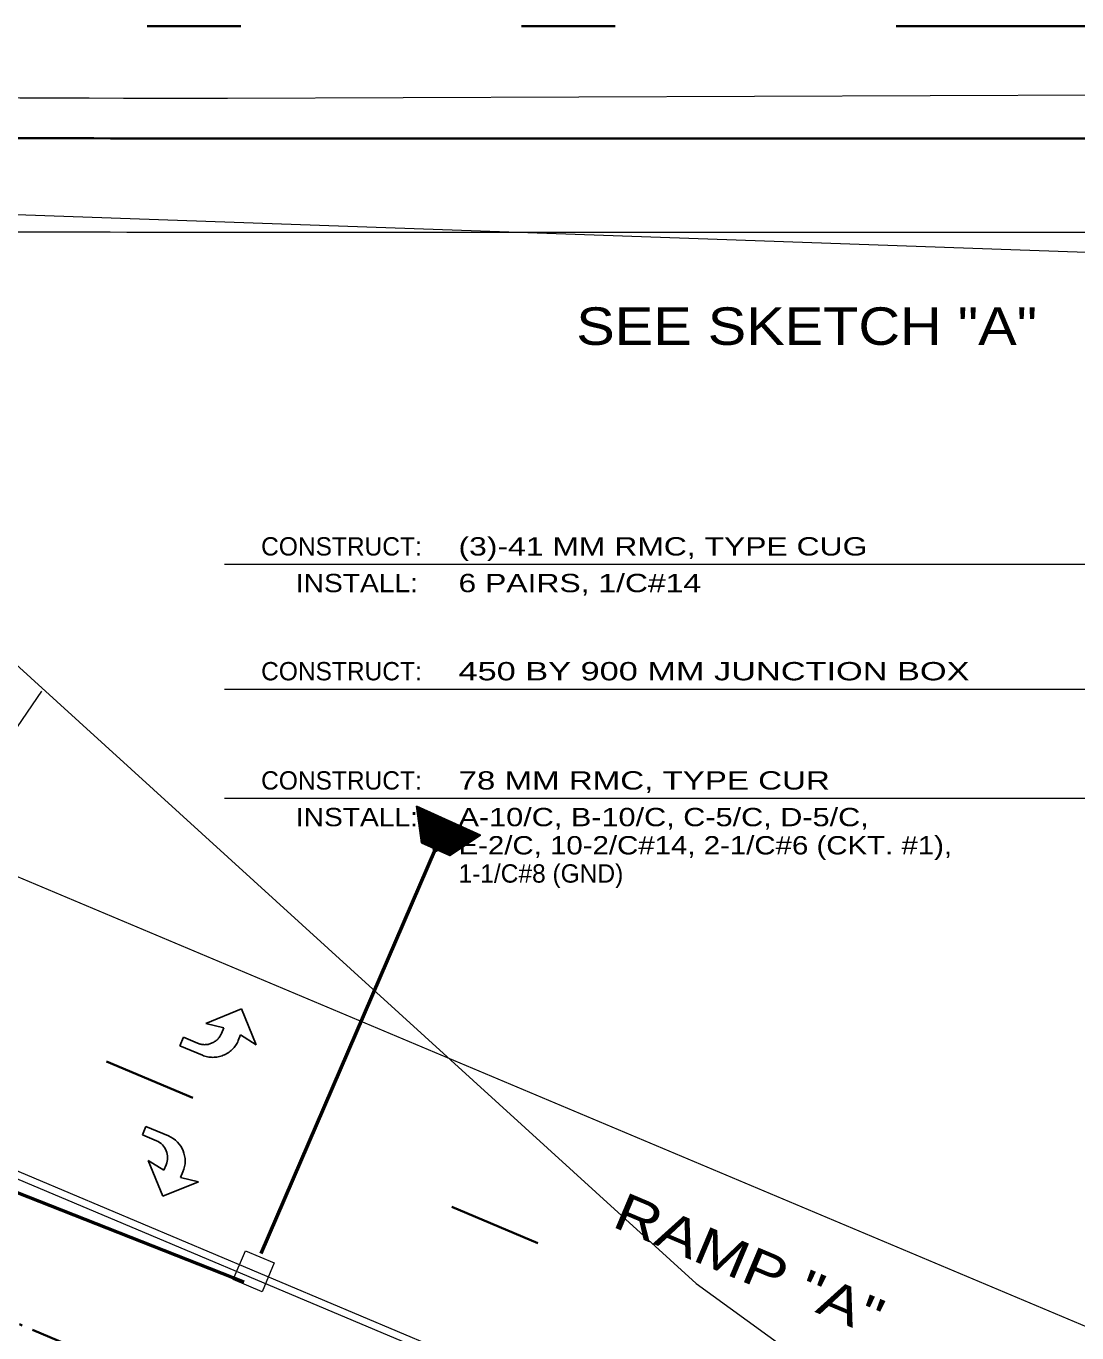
# Model space of a CAD drawing. Extents: x 168203 to 169864, y 223196 to 223870.
# Drawn here: x 168291.58 to 168325.25, y 223583.39 to 223625.27 of the extents above; entities that cross this region are included whole.
import ezdxf
from ezdxf.enums import TextEntityAlignment as Align

# ---------------------------------------------------------------- set-up
doc = ezdxf.new("R2010")
doc.units = 0
doc.header["$LTSCALE"] = 0.3
doc.header["$PDMODE"] = 32
doc.header["$PDSIZE"] = 0.15
doc.linetypes.add('DASH_DOUBLE_DOT', pattern=[9.2, 5, -1.2, 0.3, -1.2, 0.3, -1.2])
doc.linetypes.add('LONG_DASH_SHORT_DASH', pattern=[9.9, 6, -1.2, 1.5, -1.2])
for name, color, linetype, lineweight in [('1', 7, 'Continuous', 13), ('10', 7, 'Continuous', 13), ('23', 7, 'Continuous', 25), ('36', 7, 'Continuous', 35)]:
    doc.layers.add(name, color=color, linetype=linetype, lineweight=lineweight)

msp = doc.modelspace()

# ---------------------------------------------------------------- linework, layer by layer
at = {"layer": '1'}
for p, q in [((168298.0344, 223618.6676), (168341.2267, 223618.6675)), ((168237.1701, 223611.3783), (168325.032, 223574.3686)), ((168237.0809, 223611.1663), (168324.9428, 223574.1566)), ((168280.5516, 223602.5453), (168328.4093, 223582.3863))]:
    msp.add_line(p, q, dxfattribs=at)
at = {"layer": '1', "linetype": 'DASH_DOUBLE_DOT', "lineweight": 35}
msp.add_line((168235.4238, 223607.2309), (168323.2857, 223570.2212), dxfattribs=at)
at = {"layer": '1'}
msp.add_lwpolyline([(168298.2159, 223585.0983), (168298.6053, 223586.0226), (168299.5296, 223585.6332), (168299.1402, 223584.7089)], close=True, dxfattribs=at)
msp.add_arc((168297.8396, 225379.3342), 1760.6668, 269.44715, 270.00634, dxfattribs=at)
at = {"layer": '10'}
for p, q in [((168328.1441, 223608.0135), (168297.9363, 223608.0135)), ((168328.1441, 223604.0135), (168297.9363, 223604.0135)), ((168328.1441, 223600.5135), (168297.9363, 223600.5135))]:
    msp.add_line(p, q, dxfattribs=at)
at = {"layer": '23', "lineweight": 13}
for p, q in [((168298.0362, 223622.959), (168427.4519, 223623.4301)), ((168233.3078, 223621.2838), (168336.515, 223617.6326)), ((168289.1046, 223599.5914), (168292.0811, 223603.9585))]:
    msp.add_line(p, q, dxfattribs=at)
at = {"layer": '23', "lineweight": 53}
for p, q in [((168233.0416, 223610.8489), (168298.5618, 223585.0259)), ((168299.1143, 223585.9366), (168304.703, 223598.894))]:
    msp.add_line(p, q, dxfattribs=at)
at = {"layer": '23'}
for p, q in [((168304.0968, 223600.2408), (168306.1165, 223599.3222)), ((168304.1008, 223600.2115), (168306.0919, 223599.3058)), ((168304.1046, 223600.1824), (168306.0674, 223599.2896)), ((168304.1085, 223600.1531), (168306.0428, 223599.2733)), ((168304.1123, 223600.1239), (168306.0182, 223599.257)), ((168304.1162, 223600.0947), (168305.9936, 223599.2407)), ((168304.1201, 223600.0654), (168305.9691, 223599.2245)), ((168304.1239, 223600.0362), (168305.9445, 223599.2081)), ((168304.1278, 223600.007), (168305.9199, 223599.1919)), ((168304.1317, 223599.9777), (168305.8953, 223599.1756)), ((168304.1356, 223599.9485), (168305.8707, 223599.1593)), ((168304.1394, 223599.9193), (168305.8462, 223599.143)), ((168304.1433, 223599.8901), (168305.8216, 223599.1268)), ((168304.1472, 223599.8608), (168305.7971, 223599.1104)), ((168304.151, 223599.8317), (168305.7724, 223599.0942)), ((168304.1549, 223599.8024), (168305.7479, 223599.0779)), ((168304.1587, 223599.7732), (168305.7233, 223599.0616)), ((168304.1627, 223599.744), (168305.6988, 223599.0453)), ((168304.1665, 223599.7147), (168305.6741, 223599.0291)), ((168304.1704, 223599.6855), (168305.6496, 223599.0127)), ((168304.1743, 223599.6563), (168305.625, 223598.9964)), ((168304.1782, 223599.627), (168305.6005, 223598.9801)), ((168304.1821, 223599.5978), (168305.5758, 223598.9638)), ((168304.1859, 223599.5686), (168305.5513, 223598.9476)), ((168304.1898, 223599.5394), (168305.5268, 223598.9312)), ((168304.1937, 223599.5101), (168305.5022, 223598.915)), ((168304.1976, 223599.4809), (168305.4775, 223598.8987)), ((168304.2014, 223599.4517), (168305.453, 223598.8824)), ((168304.2053, 223599.4225), (168305.4285, 223598.8661)), ((168304.2092, 223599.3932), (168305.4039, 223598.8498)), ((168304.213, 223599.364), (168305.3792, 223598.8335)), ((168304.2169, 223599.3348), (168305.3547, 223598.8173)), ((168304.2207, 223599.3055), (168305.3302, 223598.8009)), ((168304.2247, 223599.2763), (168305.3056, 223598.7847)), ((168304.2285, 223599.2471), (168305.2809, 223598.7684)), ((168304.2324, 223599.2179), (168305.2565, 223598.7522)), ((168304.2362, 223599.1887), (168305.2319, 223598.7358)), ((168304.2401, 223599.1595), (168305.2073, 223598.7196)), ((168304.244, 223599.1302), (168305.1826, 223598.7033))]:
    msp.add_line(p, q, dxfattribs=at)
at = {"layer": '23', "lineweight": 13}
msp.add_lwpolyline([(168266.2242, 223619.4347), (168285.4048, 223610.1272), (168313.047, 223584.9747), (168324.8486, 223576.4143), (168350.1491, 223564.7839)], dxfattribs=at)
at = {"layer": '23'}
msp.add_lwpolyline([(168304.2478, 223599.101), (168305.1582, 223598.687), (168306.1411, 223599.3384), (168304.093, 223600.27)], close=True, dxfattribs=at)
at = {"layer": '23', "lineweight": 13}
msp.add_arc((168297.8401, 225379.3339), 1756.3749, 267.68894, 270.0064, dxfattribs=at)
at = {"layer": '23'}
msp.add_point((168304.703, 223598.894), dxfattribs=at)
at = {"layer": '36'}
for p, q in [((168295.4575, 223625.267), (168298.4575, 223625.267)), ((168307.4575, 223625.267), (168310.4575, 223625.267)), ((168319.4575, 223625.267), (168334.6542, 223625.267)), ((168298.0351, 223621.6671), (168334.851, 223621.667)), ((168294.1595, 223592.0928), (168296.9242, 223590.9282)), ((168305.2184, 223587.4345), (168307.9831, 223586.2699))]:
    msp.add_line(p, q, dxfattribs=at)
at = {"layer": '36', "linetype": 'LONG_DASH_SHORT_DASH', "lineweight": 25}
for points in [[(168297.8387, 223592.9864), (168297.9144, 223593.1662), (168297.3373, 223593.3035), (168298.487, 223593.7717), (168298.9552, 223592.622), (168298.4537, 223592.939), (168298.378, 223592.7592)], [(168297.2283, 223592.291), (168296.5092, 223592.5939), (168296.6228, 223592.8636), (168297.0722, 223592.6742)], [(168295.7557, 223589.5486), (168295.3062, 223589.7379), (168295.4198, 223590.0075), (168296.1389, 223589.7046)], [(168296.6071, 223588.5549), (168296.5314, 223588.3751), (168297.1085, 223588.2378), (168295.9588, 223587.7696), (168295.4906, 223588.9193), (168295.9921, 223588.6023), (168296.0678, 223588.7821)]]:
    msp.add_lwpolyline(points, dxfattribs=at)
at = {"layer": '36'}
msp.add_arc((168297.8402, 225379.3338), 1757.6668, 269.44715, 270.00634, dxfattribs=at)
at = {"layer": '36', "linetype": 'LONG_DASH_SHORT_DASH', "lineweight": 25}
for centre, radius, start, end in [((168297.2994, 223593.2136), 0.5852, 247.15791, 337.15791), ((168297.569, 223593.1), 0.8778, 247.15791, 337.15791), ((168295.7981, 223588.8957), 0.8778, 337.15791, 67.15791), ((168295.5284, 223589.0092), 0.5852, 337.15791, 67.15791)]:
    msp.add_arc(centre, radius, start, end, dxfattribs=at)

# ---------------------------------------------------------------- texts
at = {"layer": '1', "width": 1.25}
msp.add_text('RAMP "A"', height=1.202, rotation=337.158, dxfattribs=at).set_placement((168314.5226, 223585.043), align=Align.CENTER)
at = {"layer": '10', "width": 1.15}
msp.add_text('SEE SKETCH "A"', height=1.202, dxfattribs=at).set_placement((168316.5951, 223615.0533), align=Align.CENTER)
at = {"layer": '10'}
for s, p in [('CONSTRUCT:', (168299.111, 223608.3027)), ('CONSTRUCT:', (168299.111, 223604.3027)), ('CONSTRUCT:', (168299.111, 223600.8027)), ('1-1/C#8 (GND)                       ', (168305.4363, 223597.8206))]:
    msp.add_text(s, height=0.5873, dxfattribs=at).set_placement(p)
for s, width, p in [('(3)-41 MM RMC, TYPE CUG              ', 1.3, (168305.4363, 223608.3027)), ('6 PAIRS, 1/C#14                      ', 1.3, (168305.4363, 223607.128)), ('450 BY 900 MM JUNCTION BOX           ', 1.4, (168305.4363, 223604.3027)), ('78 MM RMC, TYPE CUR                  ', 1.35, (168305.4363, 223600.8027)), ('A-10/C, B-10/C, C-5/C, D-5/C,', 1.25, (168305.4363, 223599.628)), ('E-2/C, 10-2/C#14, 2-1/C#6 (CKT. #1),', 1.2, (168305.4363, 223598.7243))]:
    msp.add_text(s, height=0.5873, dxfattribs=dict(at, width=width)).set_placement(p)
at = {"layer": '10', "width": 1.15}
for p in [(168304.1382, 223607.128), (168304.1382, 223599.628)]:
    msp.add_text('INSTALL:', height=0.5873, dxfattribs=at).set_placement(p, align=Align.RIGHT)

doc.saveas('drawing.dxf')
